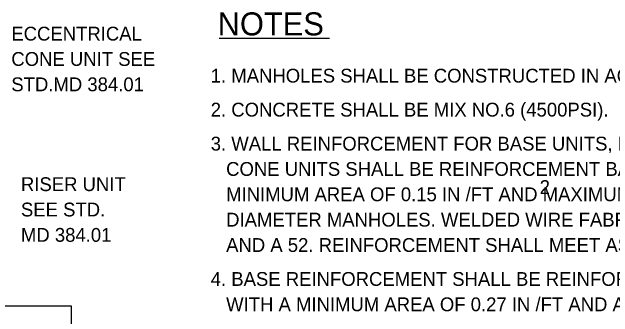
# Model space of a CAD drawing. Extents: x 26.41 to 33.74, y 20.66 to 30.6.
# Drawn here: x 29.019 to 31.625, y 25.68 to 27.003 of the extents above; entities that cross this region are included whole.
import ezdxf

# ---------------------------------------------------------------- set-up
doc = ezdxf.new("R2010")
doc.units = 0
doc.layers.add('DETL-LINE', color=7, linetype='Continuous')
doc.layers.add('DETL-NOTE', color=7, linetype='Continuous')

msp = doc.modelspace()

# ---------------------------------------------------------------- linework, layer by layer
at = {"layer": 'DETL-LINE'}
for p, q in [((29.276, 25.7264), (28.8117, 25.7264)), ((29.276, 23.135), (29.276, 25.7264))]:
    msp.add_line(p, q, dxfattribs=at)
at = {"layer": 'DETL-NOTE'}
msp.add_line((29.9171, 26.8895), (30.3956, 26.8895), dxfattribs=at)

# ---------------------------------------------------------------- texts
for s, height, p in [('NOTES', 0.09999, (29.9104, 26.9014)), ('ECCENTRICAL', 0.05998, (29.0157, 26.879)), ('CONE UNIT SEE', 0.05998, (29.0157, 26.7691)), ('1. MANHOLES SHALL BE CONSTRUCTED IN ACCORDANCE WITH AASHTO M 199.', 0.05998, (29.8803, 26.6966)), ('STD.MD 384.01', 0.05998, (29.0157, 26.6591)), ('2. CONCRETE SHALL BE MIX NO.6 (4500PSI).', 0.05998, (29.8803, 26.5493)), ('3. WALL REINFORCEMENT FOR BASE UNITS, RISER UNITS AND ECCENTRICAL ', 0.05998, (29.8803, 26.4019)), ('   CONE UNITS SHALL BE REINFORCEMENT BARS OR WELDED WIRE FABRIC WITH A', 0.05998, (29.8803, 26.292)), ('RISER UNIT', 0.05998, (29.0574, 26.2259)), ('2', 0.06, (31.3068, 26.2132)), ('   MINIMUM AREA OF 0.15 IN /FT AND MAXIMUM SPACING OF 9" FOR THE 60" ', 0.05998, (29.8803, 26.182)), ('SEE STD.', 0.05998, (29.0574, 26.1159)), ('   DIAMETER MANHOLES. WELDED WIRE FABRIC SHALL CONFORM TO ASTM A 185 ', 0.05998, (29.8803, 26.072)), ('MD 384.01', 0.05998, (29.0574, 26.0059)), ('   AND A 52. REINFORCEMENT SHALL MEET ASTM A 615, GRADE 60.', 0.05998, (29.8803, 25.962)), ('4. BASE REINFORCEMENT SHALL BE REINFORCEMENT BARS OR WELDED WIRE FABRIC', 0.05998, (29.8803, 25.8147)), ('   WITH A MINIMUM AREA OF 0.27 IN /FT AND A MAXIMUM SPACING OF 8" WITH', 0.05998, (29.8803, 25.7047))]:
    msp.add_text(s, height=height, dxfattribs=at).set_placement(p)

doc.saveas('drawing.dxf')
